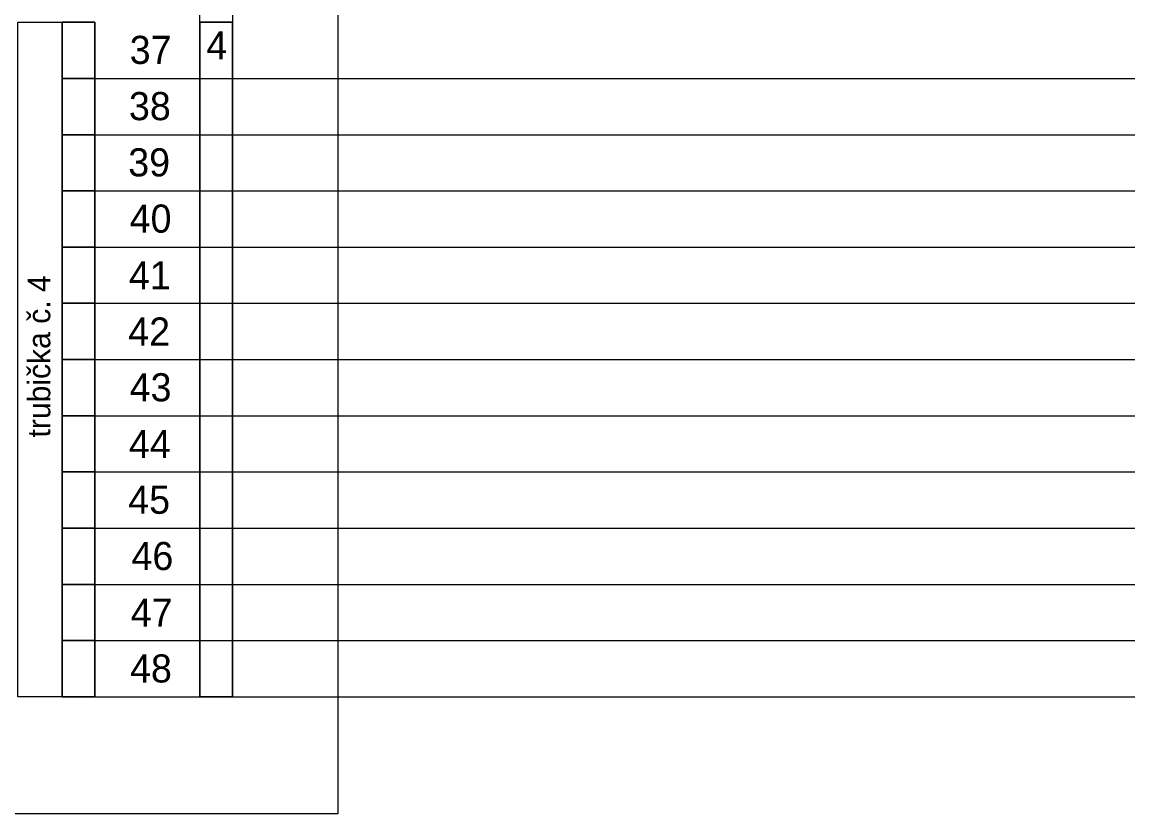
# Model space of a CAD drawing. Extents: x 1901 to 2519, y -3585 to -3154.
# Drawn here: x 2249.4 to 2318.6, y -3379.3 to -3329.7 of the extents above; entities that cross this region are included whole.
import ezdxf

# ---------------------------------------------------------------- set-up
doc = ezdxf.new("R2010")
doc.units = 0
doc.layers.add('rozvláknění', color=7, linetype='Continuous')

msp = doc.modelspace()

# ---------------------------------------------------------------- linework, layer by layer
at = {"layer": 'rozvláknění'}
for p, q in [((2253.932, -3333.246), (2385.56, -3333.245)), ((2253.932, -3336.764), (2385.56, -3336.763)), ((2253.932, -3340.282), (2385.56, -3340.281)), ((2253.932, -3343.8), (2385.56, -3343.799)), ((2253.932, -3347.318), (2385.56, -3347.318)), ((2253.932, -3350.837), (2385.56, -3350.836)), ((2253.932, -3354.355), (2385.56, -3354.354)), ((2253.932, -3357.873), (2385.56, -3357.872)), ((2253.932, -3361.391), (2385.56, -3361.39)), ((2253.932, -3364.909), (2385.56, -3364.909)), ((2253.932, -3368.428), (2385.56, -3368.427)), ((2253.932, -3371.946), (2385.56, -3371.945))]:
    msp.add_line(p, q, dxfattribs=at)
for points in [[(2230.76, -3165.344), (2269.157, -3165.343), (2269.157, -3379.277), (2230.76, -3379.277)], [(2262.556, -3371.96), (2260.515, -3371.96), (2260.515, -3287.487), (2262.556, -3287.487)], [(2249.104, -3329.727), (2251.891, -3329.727), (2251.891, -3371.942), (2249.104, -3371.942)], [(2251.891, -3329.727), (2253.932, -3329.727), (2253.932, -3333.246), (2251.891, -3333.246)], [(2251.891, -3329.727), (2253.932, -3329.727), (2253.932, -3333.246), (2251.891, -3333.246)], [(2262.556, -3371.946), (2260.515, -3371.946), (2260.515, -3329.727), (2262.556, -3329.727)], [(2251.891, -3333.246), (2253.932, -3333.246), (2253.932, -3336.764), (2251.891, -3336.764)], [(2251.891, -3333.246), (2253.932, -3333.246), (2253.932, -3336.764), (2251.891, -3336.764)], [(2251.891, -3336.764), (2253.932, -3336.764), (2253.932, -3340.282), (2251.891, -3340.282)], [(2251.891, -3336.764), (2253.932, -3336.764), (2253.932, -3340.282), (2251.891, -3340.282)], [(2251.891, -3340.282), (2253.932, -3340.282), (2253.932, -3343.8), (2251.891, -3343.8)], [(2251.891, -3340.282), (2253.932, -3340.282), (2253.932, -3343.8), (2251.891, -3343.8)], [(2251.891, -3343.8), (2253.932, -3343.8), (2253.932, -3347.318), (2251.891, -3347.318)], [(2251.891, -3343.8), (2253.932, -3343.8), (2253.932, -3347.318), (2251.891, -3347.318)], [(2251.891, -3347.318), (2253.932, -3347.318), (2253.932, -3350.837), (2251.891, -3350.837)], [(2251.891, -3347.318), (2253.932, -3347.318), (2253.932, -3350.837), (2251.891, -3350.837)], [(2251.891, -3350.837), (2253.932, -3350.837), (2253.932, -3354.355), (2251.891, -3354.355)], [(2251.891, -3350.837), (2253.932, -3350.837), (2253.932, -3354.355), (2251.891, -3354.355)], [(2251.891, -3354.355), (2253.932, -3354.355), (2253.932, -3357.873), (2251.891, -3357.873)], [(2251.891, -3354.355), (2253.932, -3354.355), (2253.932, -3357.873), (2251.891, -3357.873)], [(2251.891, -3357.873), (2253.932, -3357.873), (2253.932, -3361.391), (2251.891, -3361.391)], [(2251.891, -3357.873), (2253.932, -3357.873), (2253.932, -3361.391), (2251.891, -3361.391)], [(2251.891, -3361.391), (2253.932, -3361.391), (2253.932, -3364.909), (2251.891, -3364.909)], [(2251.891, -3361.391), (2253.932, -3361.391), (2253.932, -3364.909), (2251.891, -3364.909)], [(2251.891, -3364.909), (2253.932, -3364.909), (2253.932, -3368.428), (2251.891, -3368.428)], [(2251.891, -3364.909), (2253.932, -3364.909), (2253.932, -3368.428), (2251.891, -3368.428)], [(2251.891, -3368.428), (2253.932, -3368.428), (2253.932, -3371.946), (2251.891, -3371.946)], [(2251.891, -3368.428), (2253.932, -3368.428), (2253.932, -3371.946), (2251.891, -3371.946)]]:
    msp.add_lwpolyline(points, close=True, dxfattribs=at)
for points in [[(2251.891, -3333.246), (2253.932, -3333.246), (2253.932, -3329.727), (2251.891, -3329.727), (2251.891, -3333.246)], [(2251.891, -3333.246), (2253.932, -3333.246), (2253.932, -3329.727), (2251.891, -3329.727), (2251.891, -3333.246)], [(2251.891, -3333.246), (2253.932, -3333.246), (2253.932, -3329.727), (2251.891, -3329.727), (2251.891, -3333.246)], [(2251.891, -3333.246), (2253.932, -3333.246), (2253.932, -3329.727), (2251.891, -3329.727), (2251.891, -3333.246)], [(2251.891, -3333.246), (2253.932, -3333.246), (2253.932, -3329.727), (2251.891, -3329.727), (2251.891, -3333.246)], [(2251.891, -3333.246), (2253.932, -3333.246), (2253.932, -3329.727), (2251.891, -3329.727), (2251.891, -3333.246)], [(2251.891, -3333.246), (2253.932, -3333.246), (2253.932, -3329.727), (2251.891, -3329.727), (2251.891, -3333.246)], [(2251.891, -3333.246), (2253.932, -3333.246), (2253.932, -3329.727), (2251.891, -3329.727), (2251.891, -3333.246)], [(2251.891, -3333.246), (2253.932, -3333.246), (2253.932, -3329.727), (2251.891, -3329.727), (2251.891, -3333.246)], [(2251.891, -3333.246), (2253.932, -3333.246), (2253.932, -3329.727), (2251.891, -3329.727), (2251.891, -3333.246)], [(2262.556, -3329.727), (2260.515, -3329.727), (2260.515, -3371.946), (2262.556, -3371.946), (2262.556, -3329.727)], [(2262.556, -3329.727), (2260.515, -3329.727), (2260.515, -3371.946), (2262.556, -3371.946), (2262.556, -3329.727)], [(2262.556, -3329.727), (2260.515, -3329.727), (2260.515, -3371.946), (2262.556, -3371.946), (2262.556, -3329.727)], [(2262.556, -3329.727), (2260.515, -3329.727), (2260.515, -3371.946), (2262.556, -3371.946), (2262.556, -3329.727)], [(2262.556, -3329.727), (2260.515, -3329.727), (2260.515, -3371.946), (2262.556, -3371.946), (2262.556, -3329.727)], [(2262.556, -3329.727), (2260.515, -3329.727), (2260.515, -3371.946), (2262.556, -3371.946), (2262.556, -3329.727)], [(2251.891, -3333.244), (2251.891, -3368.444)], [(2251.891, -3336.764), (2253.932, -3336.764), (2253.932, -3333.246), (2251.891, -3333.246), (2251.891, -3336.764)], [(2251.891, -3336.764), (2253.932, -3336.764), (2253.932, -3333.246), (2251.891, -3333.246), (2251.891, -3336.764)], [(2251.891, -3336.764), (2253.932, -3336.764), (2253.932, -3333.246), (2251.891, -3333.246), (2251.891, -3336.764)], [(2251.891, -3336.764), (2253.932, -3336.764), (2253.932, -3333.246), (2251.891, -3333.246), (2251.891, -3336.764)], [(2251.891, -3336.764), (2253.932, -3336.764), (2253.932, -3333.246), (2251.891, -3333.246), (2251.891, -3336.764)], [(2251.891, -3336.764), (2253.932, -3336.764), (2253.932, -3333.246), (2251.891, -3333.246), (2251.891, -3336.764)], [(2251.891, -3336.764), (2253.932, -3336.764), (2253.932, -3333.246), (2251.891, -3333.246), (2251.891, -3336.764)], [(2251.891, -3336.764), (2253.932, -3336.764), (2253.932, -3333.246), (2251.891, -3333.246), (2251.891, -3336.764)], [(2251.891, -3336.764), (2253.932, -3336.764), (2253.932, -3333.246), (2251.891, -3333.246), (2251.891, -3336.764)], [(2251.891, -3336.764), (2253.932, -3336.764), (2253.932, -3333.246), (2251.891, -3333.246), (2251.891, -3336.764)], [(2251.891, -3340.282), (2253.932, -3340.282), (2253.932, -3336.764), (2251.891, -3336.764), (2251.891, -3340.282)], [(2251.891, -3340.282), (2253.932, -3340.282), (2253.932, -3336.764), (2251.891, -3336.764), (2251.891, -3340.282)], [(2251.891, -3340.282), (2253.932, -3340.282), (2253.932, -3336.764), (2251.891, -3336.764), (2251.891, -3340.282)], [(2251.891, -3340.282), (2253.932, -3340.282), (2253.932, -3336.764), (2251.891, -3336.764), (2251.891, -3340.282)], [(2251.891, -3340.282), (2253.932, -3340.282), (2253.932, -3336.764), (2251.891, -3336.764), (2251.891, -3340.282)], [(2251.891, -3340.282), (2253.932, -3340.282), (2253.932, -3336.764), (2251.891, -3336.764), (2251.891, -3340.282)], [(2251.891, -3340.282), (2253.932, -3340.282), (2253.932, -3336.764), (2251.891, -3336.764), (2251.891, -3340.282)], [(2251.891, -3340.282), (2253.932, -3340.282), (2253.932, -3336.764), (2251.891, -3336.764), (2251.891, -3340.282)], [(2251.891, -3340.282), (2253.932, -3340.282), (2253.932, -3336.764), (2251.891, -3336.764), (2251.891, -3340.282)], [(2251.891, -3340.282), (2253.932, -3340.282), (2253.932, -3336.764), (2251.891, -3336.764), (2251.891, -3340.282)], [(2251.891, -3343.8), (2253.932, -3343.8), (2253.932, -3340.282), (2251.891, -3340.282), (2251.891, -3343.8)], [(2251.891, -3343.8), (2253.932, -3343.8), (2253.932, -3340.282), (2251.891, -3340.282), (2251.891, -3343.8)], [(2251.891, -3343.8), (2253.932, -3343.8), (2253.932, -3340.282), (2251.891, -3340.282), (2251.891, -3343.8)], [(2251.891, -3343.8), (2253.932, -3343.8), (2253.932, -3340.282), (2251.891, -3340.282), (2251.891, -3343.8)], [(2251.891, -3343.8), (2253.932, -3343.8), (2253.932, -3340.282), (2251.891, -3340.282), (2251.891, -3343.8)], [(2251.891, -3343.8), (2253.932, -3343.8), (2253.932, -3340.282), (2251.891, -3340.282), (2251.891, -3343.8)], [(2251.891, -3343.8), (2253.932, -3343.8), (2253.932, -3340.282), (2251.891, -3340.282), (2251.891, -3343.8)], [(2251.891, -3343.8), (2253.932, -3343.8), (2253.932, -3340.282), (2251.891, -3340.282), (2251.891, -3343.8)], [(2251.891, -3343.8), (2253.932, -3343.8), (2253.932, -3340.282), (2251.891, -3340.282), (2251.891, -3343.8)], [(2251.891, -3343.8), (2253.932, -3343.8), (2253.932, -3340.282), (2251.891, -3340.282), (2251.891, -3343.8)], [(2251.891, -3347.318), (2253.932, -3347.318), (2253.932, -3343.8), (2251.891, -3343.8), (2251.891, -3347.318)], [(2251.891, -3347.318), (2253.932, -3347.318), (2253.932, -3343.8), (2251.891, -3343.8), (2251.891, -3347.318)], [(2251.891, -3347.318), (2253.932, -3347.318), (2253.932, -3343.8), (2251.891, -3343.8), (2251.891, -3347.318)], [(2251.891, -3347.318), (2253.932, -3347.318), (2253.932, -3343.8), (2251.891, -3343.8), (2251.891, -3347.318)], [(2251.891, -3347.318), (2253.932, -3347.318), (2253.932, -3343.8), (2251.891, -3343.8), (2251.891, -3347.318)], [(2251.891, -3347.318), (2253.932, -3347.318), (2253.932, -3343.8), (2251.891, -3343.8), (2251.891, -3347.318)], [(2251.891, -3347.318), (2253.932, -3347.318), (2253.932, -3343.8), (2251.891, -3343.8), (2251.891, -3347.318)], [(2251.891, -3347.318), (2253.932, -3347.318), (2253.932, -3343.8), (2251.891, -3343.8), (2251.891, -3347.318)], [(2251.891, -3347.318), (2253.932, -3347.318), (2253.932, -3343.8), (2251.891, -3343.8), (2251.891, -3347.318)], [(2251.891, -3347.318), (2253.932, -3347.318), (2253.932, -3343.8), (2251.891, -3343.8), (2251.891, -3347.318)], [(2251.891, -3350.837), (2253.932, -3350.837), (2253.932, -3347.318), (2251.891, -3347.318), (2251.891, -3350.837)], [(2251.891, -3350.837), (2253.932, -3350.837), (2253.932, -3347.318), (2251.891, -3347.318), (2251.891, -3350.837)], [(2251.891, -3350.837), (2253.932, -3350.837), (2253.932, -3347.318), (2251.891, -3347.318), (2251.891, -3350.837)], [(2251.891, -3350.837), (2253.932, -3350.837), (2253.932, -3347.318), (2251.891, -3347.318), (2251.891, -3350.837)], [(2251.891, -3350.837), (2253.932, -3350.837), (2253.932, -3347.318), (2251.891, -3347.318), (2251.891, -3350.837)], [(2251.891, -3350.837), (2253.932, -3350.837), (2253.932, -3347.318), (2251.891, -3347.318), (2251.891, -3350.837)], [(2251.891, -3350.837), (2253.932, -3350.837), (2253.932, -3347.318), (2251.891, -3347.318), (2251.891, -3350.837)], [(2251.891, -3350.837), (2253.932, -3350.837), (2253.932, -3347.318), (2251.891, -3347.318), (2251.891, -3350.837)], [(2251.891, -3350.837), (2253.932, -3350.837), (2253.932, -3347.318), (2251.891, -3347.318), (2251.891, -3350.837)], [(2251.891, -3350.837), (2253.932, -3350.837), (2253.932, -3347.318), (2251.891, -3347.318), (2251.891, -3350.837)], [(2251.891, -3354.355), (2253.932, -3354.355), (2253.932, -3350.837), (2251.891, -3350.837), (2251.891, -3354.355)], [(2251.891, -3354.355), (2253.932, -3354.355), (2253.932, -3350.837), (2251.891, -3350.837), (2251.891, -3354.355)], [(2251.891, -3354.355), (2253.932, -3354.355), (2253.932, -3350.837), (2251.891, -3350.837), (2251.891, -3354.355)], [(2251.891, -3354.355), (2253.932, -3354.355), (2253.932, -3350.837), (2251.891, -3350.837), (2251.891, -3354.355)], [(2251.891, -3354.355), (2253.932, -3354.355), (2253.932, -3350.837), (2251.891, -3350.837), (2251.891, -3354.355)], [(2251.891, -3354.355), (2253.932, -3354.355), (2253.932, -3350.837), (2251.891, -3350.837), (2251.891, -3354.355)], [(2251.891, -3354.355), (2253.932, -3354.355), (2253.932, -3350.837), (2251.891, -3350.837), (2251.891, -3354.355)], [(2251.891, -3354.355), (2253.932, -3354.355), (2253.932, -3350.837), (2251.891, -3350.837), (2251.891, -3354.355)], [(2251.891, -3354.355), (2253.932, -3354.355), (2253.932, -3350.837), (2251.891, -3350.837), (2251.891, -3354.355)], [(2251.891, -3354.355), (2253.932, -3354.355), (2253.932, -3350.837), (2251.891, -3350.837), (2251.891, -3354.355)], [(2251.891, -3357.873), (2253.932, -3357.873), (2253.932, -3354.355), (2251.891, -3354.355), (2251.891, -3357.873)], [(2251.891, -3357.873), (2253.932, -3357.873), (2253.932, -3354.355), (2251.891, -3354.355), (2251.891, -3357.873)], [(2251.891, -3357.873), (2253.932, -3357.873), (2253.932, -3354.355), (2251.891, -3354.355), (2251.891, -3357.873)], [(2251.891, -3357.873), (2253.932, -3357.873), (2253.932, -3354.355), (2251.891, -3354.355), (2251.891, -3357.873)], [(2251.891, -3357.873), (2253.932, -3357.873), (2253.932, -3354.355), (2251.891, -3354.355), (2251.891, -3357.873)], [(2251.891, -3357.873), (2253.932, -3357.873), (2253.932, -3354.355), (2251.891, -3354.355), (2251.891, -3357.873)], [(2251.891, -3357.873), (2253.932, -3357.873), (2253.932, -3354.355), (2251.891, -3354.355), (2251.891, -3357.873)], [(2251.891, -3357.873), (2253.932, -3357.873), (2253.932, -3354.355), (2251.891, -3354.355), (2251.891, -3357.873)], [(2251.891, -3357.873), (2253.932, -3357.873), (2253.932, -3354.355), (2251.891, -3354.355), (2251.891, -3357.873)], [(2251.891, -3357.873), (2253.932, -3357.873), (2253.932, -3354.355), (2251.891, -3354.355), (2251.891, -3357.873)], [(2251.891, -3361.391), (2253.932, -3361.391), (2253.932, -3357.873), (2251.891, -3357.873), (2251.891, -3361.391)], [(2251.891, -3361.391), (2253.932, -3361.391), (2253.932, -3357.873), (2251.891, -3357.873), (2251.891, -3361.391)], [(2251.891, -3361.391), (2253.932, -3361.391), (2253.932, -3357.873), (2251.891, -3357.873), (2251.891, -3361.391)], [(2251.891, -3361.391), (2253.932, -3361.391), (2253.932, -3357.873), (2251.891, -3357.873), (2251.891, -3361.391)], [(2251.891, -3361.391), (2253.932, -3361.391), (2253.932, -3357.873), (2251.891, -3357.873), (2251.891, -3361.391)], [(2251.891, -3361.391), (2253.932, -3361.391), (2253.932, -3357.873), (2251.891, -3357.873), (2251.891, -3361.391)], [(2251.891, -3361.391), (2253.932, -3361.391), (2253.932, -3357.873), (2251.891, -3357.873), (2251.891, -3361.391)], [(2251.891, -3361.391), (2253.932, -3361.391), (2253.932, -3357.873), (2251.891, -3357.873), (2251.891, -3361.391)], [(2251.891, -3361.391), (2253.932, -3361.391), (2253.932, -3357.873), (2251.891, -3357.873), (2251.891, -3361.391)], [(2251.891, -3361.391), (2253.932, -3361.391), (2253.932, -3357.873), (2251.891, -3357.873), (2251.891, -3361.391)], [(2251.891, -3364.909), (2253.932, -3364.909), (2253.932, -3361.391), (2251.891, -3361.391), (2251.891, -3364.909)], [(2251.891, -3364.909), (2253.932, -3364.909), (2253.932, -3361.391), (2251.891, -3361.391), (2251.891, -3364.909)], [(2251.891, -3364.909), (2253.932, -3364.909), (2253.932, -3361.391), (2251.891, -3361.391), (2251.891, -3364.909)], [(2251.891, -3364.909), (2253.932, -3364.909), (2253.932, -3361.391), (2251.891, -3361.391), (2251.891, -3364.909)], [(2251.891, -3364.909), (2253.932, -3364.909), (2253.932, -3361.391), (2251.891, -3361.391), (2251.891, -3364.909)], [(2251.891, -3364.909), (2253.932, -3364.909), (2253.932, -3361.391), (2251.891, -3361.391), (2251.891, -3364.909)], [(2251.891, -3364.909), (2253.932, -3364.909), (2253.932, -3361.391), (2251.891, -3361.391), (2251.891, -3364.909)], [(2251.891, -3364.909), (2253.932, -3364.909), (2253.932, -3361.391), (2251.891, -3361.391), (2251.891, -3364.909)], [(2251.891, -3364.909), (2253.932, -3364.909), (2253.932, -3361.391), (2251.891, -3361.391), (2251.891, -3364.909)], [(2251.891, -3364.909), (2253.932, -3364.909), (2253.932, -3361.391), (2251.891, -3361.391), (2251.891, -3364.909)], [(2251.891, -3368.428), (2253.932, -3368.428), (2253.932, -3364.909), (2251.891, -3364.909), (2251.891, -3368.428)], [(2251.891, -3368.428), (2253.932, -3368.428), (2253.932, -3364.909), (2251.891, -3364.909), (2251.891, -3368.428)], [(2251.891, -3368.428), (2253.932, -3368.428), (2253.932, -3364.909), (2251.891, -3364.909), (2251.891, -3368.428)], [(2251.891, -3368.428), (2253.932, -3368.428), (2253.932, -3364.909), (2251.891, -3364.909), (2251.891, -3368.428)], [(2251.891, -3368.428), (2253.932, -3368.428), (2253.932, -3364.909), (2251.891, -3364.909), (2251.891, -3368.428)], [(2251.891, -3368.428), (2253.932, -3368.428), (2253.932, -3364.909), (2251.891, -3364.909), (2251.891, -3368.428)], [(2251.891, -3368.428), (2253.932, -3368.428), (2253.932, -3364.909), (2251.891, -3364.909), (2251.891, -3368.428)], [(2251.891, -3368.428), (2253.932, -3368.428), (2253.932, -3364.909), (2251.891, -3364.909), (2251.891, -3368.428)], [(2251.891, -3368.428), (2253.932, -3368.428), (2253.932, -3364.909), (2251.891, -3364.909), (2251.891, -3368.428)], [(2251.891, -3368.428), (2253.932, -3368.428), (2253.932, -3364.909), (2251.891, -3364.909), (2251.891, -3368.428)], [(2251.891, -3371.946), (2253.932, -3371.946), (2253.932, -3368.428), (2251.891, -3368.428), (2251.891, -3371.946)], [(2251.891, -3371.946), (2253.932, -3371.946), (2253.932, -3368.428), (2251.891, -3368.428), (2251.891, -3371.946)], [(2251.891, -3371.946), (2253.932, -3371.946), (2253.932, -3368.428), (2251.891, -3368.428), (2251.891, -3371.946)], [(2251.891, -3371.946), (2253.932, -3371.946), (2253.932, -3368.428), (2251.891, -3368.428), (2251.891, -3371.946)], [(2251.891, -3371.946), (2253.932, -3371.946), (2253.932, -3368.428), (2251.891, -3368.428), (2251.891, -3371.946)], [(2251.891, -3371.946), (2253.932, -3371.946), (2253.932, -3368.428), (2251.891, -3368.428), (2251.891, -3371.946)], [(2251.891, -3371.946), (2253.932, -3371.946), (2253.932, -3368.428), (2251.891, -3368.428), (2251.891, -3371.946)], [(2251.891, -3371.946), (2253.932, -3371.946), (2253.932, -3368.428), (2251.891, -3368.428), (2251.891, -3371.946)], [(2251.891, -3371.946), (2253.932, -3371.946), (2253.932, -3368.428), (2251.891, -3368.428), (2251.891, -3371.946)], [(2251.891, -3371.946), (2253.932, -3371.946), (2253.932, -3368.428), (2251.891, -3368.428), (2251.891, -3371.946)]]:
    msp.add_lwpolyline(points, dxfattribs=at)

# ---------------------------------------------------------------- texts
for s, p in [('37', (2256.113, -3332.334)), ('4', (2260.914, -3332.053)), ('4', (2260.914, -3332.053)), ('38', (2256.066, -3335.854)), ('39', (2256.024, -3339.374)), ('40', (2256.113, -3342.894)), ('41', (2256.066, -3346.444)), ('42', (2256.024, -3349.964)), ('43', (2256.113, -3353.454)), ('44', (2256.066, -3357.004)), ('45', (2256.024, -3360.494)), ('46', (2256.226, -3364.014)), ('47', (2256.179, -3367.564)), ('48', (2256.137, -3371.054))]:
    msp.add_text(s, height=1.76, dxfattribs=at).set_placement(p)
msp.add_text('trubička č. 4', height=1.408, rotation=90, dxfattribs=at).set_placement((2251.139, -3355.716))

doc.saveas('drawing.dxf')
